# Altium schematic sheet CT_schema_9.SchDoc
size 297 x 239 mm
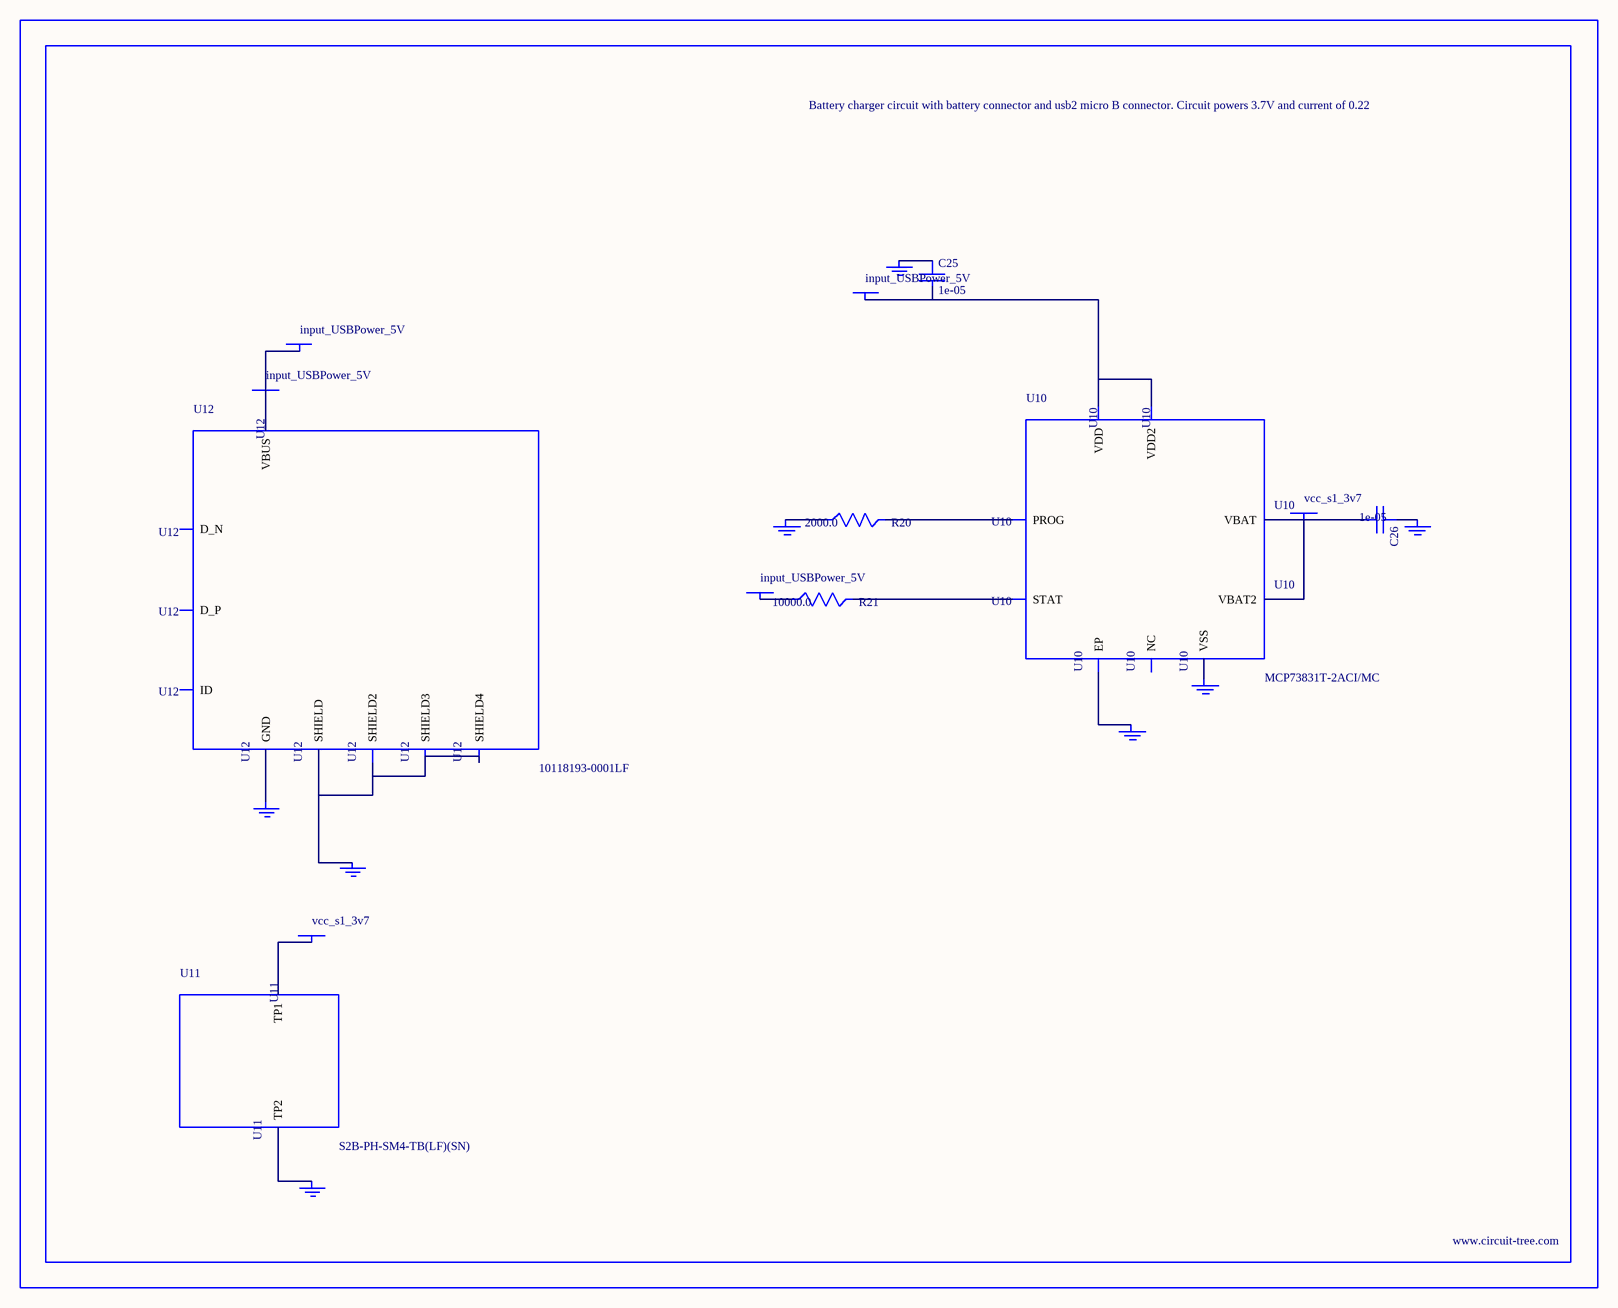
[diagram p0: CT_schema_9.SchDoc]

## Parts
BORDER8  (no value)
C25  1e-05  [C1206]
C26  1e-05  [C1206]
GND_INSTANCE_8_0  (no value)
GND_INSTANCE_8_1  (no value)
GND_INSTANCE_8_2  (no value)
GND_INSTANCE_8_3  (no value)
GND_INSTANCE_8_4  (no value)
GND_INSTANCE_8_5  (no value)
GND_INSTANCE_8_6  (no value)
GND_INSTANCE_8_7  (no value)
POWER_INSTANCE_8_0  input_USBPower_5V
POWER_INSTANCE_8_1  input_USBPower_5V
POWER_INSTANCE_8_2  vcc_s1_3v7
POWER_INSTANCE_8_3  vcc_s1_3v7
POWER_INSTANCE_8_4  input_USBPower_5V
POWER_INSTANCE_8_5  input_USBPower_5V
R20  2000.0  [R0603]
R21  10000.0  [R0603]
U10  MCP73831T-2ACI/MC  [DFN8_2X3MC]
U11  S2B-PH-SM4-TB(LF)(SN)  [JST-2-SMD]
U12  10118193-0001LF  [FCI_10118193-0001LF]

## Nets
NetC25_1: C25.1 GND_INSTANCE_8_0.0(GND)
NetC25_2: C25.2 POWER_INSTANCE_8_0.0(PWR) U10.1(VDD) U10.2(VDD2)
NetC26_1: C26.1 GND_INSTANCE_8_1.0(GND)
NetC26_2: C26.2 POWER_INSTANCE_8_2.0(PWR) U10.3(VBAT) U10.4(VBAT2)
NetGND_INSTANCE_8_2_0: GND_INSTANCE_8_2.0(GND) R20.1
NetGND_INSTANCE_8_3_0: GND_INSTANCE_8_3.0(GND) U10.9(EP)
NetGND_INSTANCE_8_4_0: GND_INSTANCE_8_4.0(GND) U10.6(VSS)
NetGND_INSTANCE_8_5_0: GND_INSTANCE_8_5.0(GND) U11.2(TP2)
NetGND_INSTANCE_8_6_0: GND_INSTANCE_8_6.0(GND) U12.6(SHIELD) U12.7(SHIELD2) U12.8(SHIELD3) U12.9(SHIELD4)
NetGND_INSTANCE_8_7_0: GND_INSTANCE_8_7.0(GND) U12.5(GND)
NetPOWER_INSTANCE_8_1_0: POWER_INSTANCE_8_1.0(PWR) R21.1
NetPOWER_INSTANCE_8_3_0: POWER_INSTANCE_8_3.0(PWR) U11.1(TP1)
NetPOWER_INSTANCE_8_4_0: POWER_INSTANCE_8_4.0(PWR) POWER_INSTANCE_8_5.0(PWR) U12.1(VBUS)
NetR20_2: R20.2 U10.8(PROG)
NetR21_2: R21.2 U10.5(STAT)

Not connected (* = marked no-connect by the designer): U10 7(NC); U12 2(D_N) 3(D_P) 4(ID)

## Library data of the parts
BORDER8 = BORDER_PAGE8
C25 C26 = C1206C106K3RACTU
GND_INSTANCE_8_0-GND_INSTANCE_8_7 = GND
POWER_INSTANCE_8_0-POWER_INSTANCE_8_5 = PWR
R20 = RC0603JR-072KL
R21 = RC0603JR-0710KL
